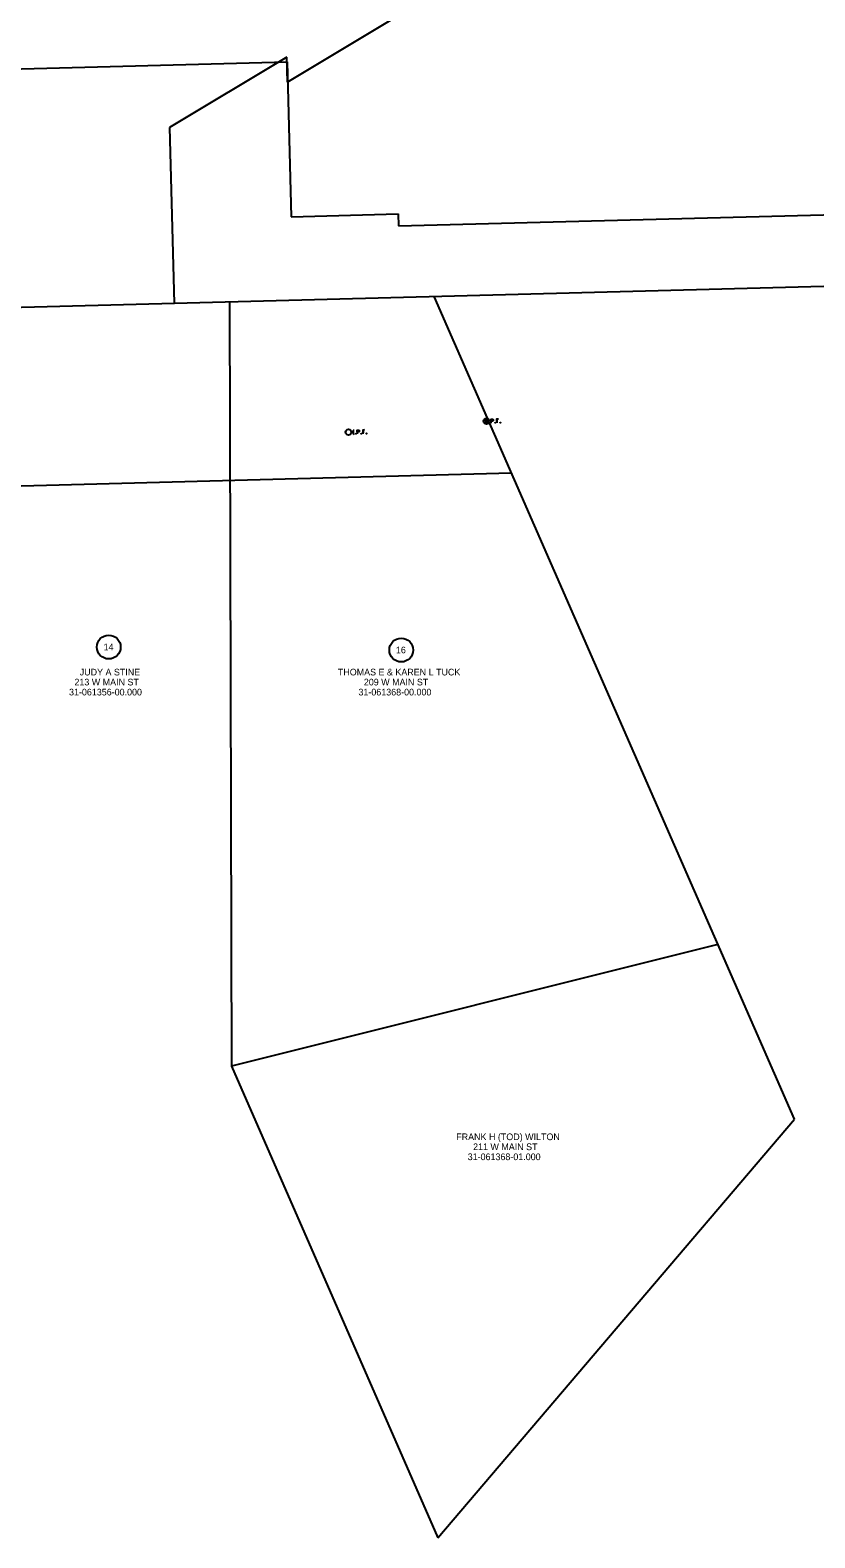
# Model space of a CAD drawing. Extents: x 200073 to 202746, y 352381 to 357578.
# Drawn here: x 201436 to 201765, y 354457 to 355089 of the extents above; entities that cross this region are included whole.
import ezdxf

# ---------------------------------------------------------------- set-up
doc = ezdxf.new("R2010")
doc.units = 0
for name, color, linetype in [('_CIVIL_CONSTRUCTION', 7, 'Continuous'), ('RW_X_CL_100_Bearings', 7, 'Continuous'), ('RW_X_CL_100_Cardinal_Points', 7, 'Continuous'), ('RW_X_CL_100_Stations', 7, 'Continuous'), ('RW_X_CL_500_Bearings', 7, 'Continuous'), ('SC_Scratch1', 7, 'Continuous')]:
    doc.layers.add(name, color=color, linetype=linetype)

msp = doc.modelspace()

# ---------------------------------------------------------------- linework, layer by layer
at = {"layer": '_CIVIL_CONSTRUCTION'}
msp.add_line((200083.32, 354937.76), (202745.29, 355007.24), dxfattribs=at)
at = {"layer": 'RW_X_CL_100_Bearings'}
for p, q in [((201758.42, 355196.44), (201543.73, 355067.47)), ((201543.46, 355077.95), (201494.22, 355048.37)), ((201543.73, 355067.47), (201543.46, 355077.95)), ((201494.22, 355048.37), (201496.19, 354974.64)), ((201519.41, 354975.24), (201520.13, 354654.43)), ((201756.42, 354632.2), (201605.37, 354977.2)), ((201724.33, 354705.49), (201520.13, 354654.43)), ((201520.13, 354654.43), (201606.71, 354456.53)), ((201606.71, 354456.53), (201756.42, 354632.2))]:
    msp.add_line(p, q, dxfattribs=at)
at = {"layer": 'RW_X_CL_100_Cardinal_Points'}
msp.add_line((201414.09, 354897.58), (201637.62, 354903.42), dxfattribs=at)
at = {"layer": 'RW_X_CL_100_Stations'}
for centre in [(201468.67, 354830.38), (201591.43, 354829.12)]:
    msp.add_circle(centre, 5, dxfattribs=at)
at = {"layer": 'RW_X_CL_500_Bearings'}
for p, q in [((200731.62, 355054.72), (201543.51, 355075.91)), ((201543.51, 355075.91), (201545.21, 355010.93)), ((201545.21, 355010.93), (201590.19, 355012.1)), ((201590.19, 355012.1), (201590.32, 355007.1)), ((201590.32, 355007.1), (201890.22, 355014.93))]:
    msp.add_line(p, q, dxfattribs=at)
at = {"layer": 'SC_Scratch1'}
for points in [[(201571.24, 354921.37), (201571.6, 354921.38)], [(201571.45, 354919.77), (201571.42, 354921.37)], [(201573.01, 354919.8), (201572.98, 354921.4), (201573.51, 354921.41), (201573.57, 354921.4), (201573.65, 354921.38), (201573.68, 354921.35), (201573.71, 354921.33), (201573.76, 354921.27), (201573.79, 354921.2), (201573.82, 354921.1), (201573.82, 354920.95), (201573.81, 354920.9), (201573.79, 354920.83), (201573.75, 354920.74), (201573.7, 354920.7), (201573.67, 354920.67), (201573.62, 354920.65), (201573.53, 354920.63), (201573, 354920.62)], [(201575.99, 354921.46), (201575.23, 354921.44), (201575.26, 354919.85)], [(201575.25, 354920.66), (201575.79, 354920.67)], [(201629.21, 354924.38), (201629.18, 354925.97), (201629.71, 354925.98), (201629.77, 354925.97), (201629.84, 354925.95), (201629.88, 354925.92), (201629.91, 354925.9), (201629.96, 354925.84), (201629.99, 354925.78), (201630.01, 354925.68), (201630.02, 354925.52), (201630.01, 354925.47), (201629.99, 354925.4), (201629.94, 354925.31), (201629.9, 354925.27), (201629.87, 354925.24), (201629.81, 354925.22), (201629.73, 354925.2), (201629.2, 354925.19)], [(201630.85, 354924.62), (201630.91, 354924.62), (201630.94, 354924.6), (201630.97, 354924.55), (201630.97, 354924.48), (201630.94, 354924.43), (201630.91, 354924.41), (201630.85, 354924.41), (201630.82, 354924.43), (201630.79, 354924.48), (201630.79, 354924.54), (201630.82, 354924.59), (201630.85, 354924.62)], [(201632.19, 354926.03), (201631.43, 354926.02), (201631.46, 354924.42)], [(201631.45, 354925.24), (201631.99, 354925.25)], [(201633, 354924.66), (201633.05, 354924.66), (201633.09, 354924.64), (201633.12, 354924.59), (201633.12, 354924.52), (201633.09, 354924.47), (201633.06, 354924.45), (201633, 354924.45), (201632.97, 354924.47), (201632.94, 354924.52), (201632.93, 354924.58), (201632.97, 354924.64), (201633, 354924.66)], [(201571.27, 354919.77), (201571.63, 354919.78)], [(201572.4, 354920.01), (201572.46, 354920.01), (201572.49, 354919.98), (201572.53, 354919.93), (201572.53, 354919.87), (201572.5, 354919.82), (201572.46, 354919.79), (201572.41, 354919.79), (201572.38, 354919.82), (201572.34, 354919.87), (201572.34, 354919.93), (201572.37, 354919.98), (201572.4, 354920.01)], [(201574.65, 354920.05), (201574.71, 354920.05), (201574.74, 354920.02), (201574.78, 354919.97), (201574.78, 354919.91), (201574.74, 354919.86), (201574.71, 354919.83), (201574.66, 354919.83), (201574.62, 354919.86), (201574.59, 354919.91), (201574.59, 354919.97), (201574.62, 354920.02), (201574.65, 354920.05)], [(201576.8, 354920.09), (201576.86, 354920.09), (201576.89, 354920.07), (201576.92, 354920.02), (201576.93, 354919.95), (201576.89, 354919.9), (201576.86, 354919.88), (201576.81, 354919.87), (201576.77, 354919.9), (201576.74, 354919.95), (201576.74, 354920.01), (201576.77, 354920.06), (201576.8, 354920.09)]]:
    msp.add_lwpolyline(points, dxfattribs=at)
for centre, radius in [((201569.24, 354920.53), 1.2), ((201627.2, 354925.14), 1.2), ((201627.2, 354925.14), 0.495)]:
    msp.add_circle(centre, radius, dxfattribs=at)

# ---------------------------------------------------------------- texts
at = {"layer": 'RW_X_CL_100_Stations'}
for s, p in [('14', (201466.52, 354828.98)), ('16', (201589.19, 354827.72)), ('JUDY A STINE', (201456.5, 354818.45)), ('THOMAS E & KAREN L TUCK', (201564.83, 354818.45)), ('213 W MAIN ST', (201454.28, 354814.25)), ('209 W MAIN ST', (201575.72, 354814.25)), ('31-061356-00.000', (201452.01, 354810.05)), ('31-061368-00.000', (201573.46, 354810.05)), ('FRANK H (TOD) WILTON', (201614.5, 354623.43)), ('31-061368-01.000', (201619.3, 354615.03)), ('211 W MAIN ST', (201621.56, 354619.23))]:
    msp.add_text(s, height=2.8, rotation=359.99853, dxfattribs=at).set_placement(p)

doc.saveas('drawing.dxf')
